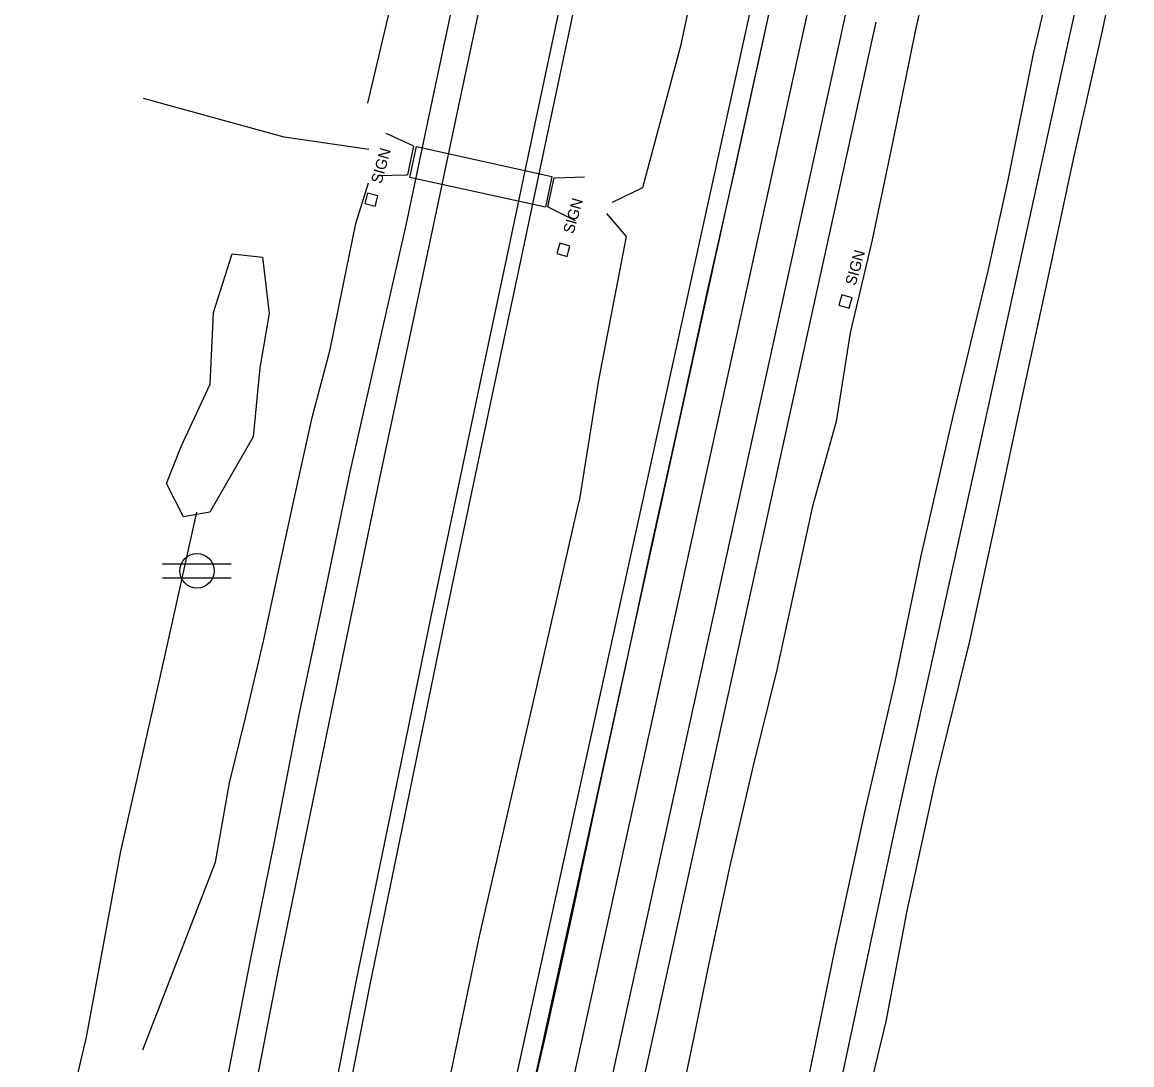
# Model space of a CAD drawing. Extents: x 14105231 to 14123593, y 8636972 to 8671693.
# Drawn here: x 14107983.5 to 14108338.7, y 8640678.7 to 8641012.4 of the extents above; entities that cross this region are included whole.
import ezdxf

# ---------------------------------------------------------------- set-up
doc = ezdxf.new("R2010")
doc.units = 0
for name, color, linetype in [('dsn3DCenterLine', 7, 'Continuous'), ('dsn3DPavementTop', 7, 'Continuous'), ('dsn3DShoulderTop', 7, 'Continuous'), ('PhoDrainageArrow', 7, 'Continuous'), ('PhoEdgeRoadPaved', 7, 'Continuous'), ('PhoEdgeShoulderPaved', 7, 'Continuous'), ('PhoEdgeShoulderUnpaved', 7, 'Continuous'), ('PhoFence', 7, 'Continuous'), ('PhoRailRoadTrack', 7, 'Continuous'), ('PhoRoadPoints', 7, 'Continuous'), ('PhoVegetation', 7, 'Continuous'), ('SurCulvert', 7, 'Continuous'), ('SurDrainageArrowUp', 7, 'Continuous'), ('SurUtilityPoleCell', 7, 'Continuous')]:
    doc.layers.add(name, color=color, linetype=linetype)

msp = doc.modelspace()

# ---------------------------------------------------------------- linework, layer by layer
at = {"layer": 'dsn3DCenterLine'}
msp.add_lwpolyline([(14108126.97, 8640523.99), (14108234.25, 8641012.34), (14108235.32, 8641017.22)], dxfattribs=at)
at = {"layer": 'dsn3DPavementTop'}
for points in [[(14108087.36, 8640399.59), (14108222.53, 8641014.92)], [(14108138.69, 8640521.41), (14108245.97, 8641009.77), (14108247.04, 8641014.65)]]:
    msp.add_lwpolyline(points, dxfattribs=at)
at = {"layer": 'dsn3DShoulderTop'}
for points in [[(14108123.34, 8640591.33), (14108124.41, 8640596.22), (14108216.67, 8641016.2)], [(14108123.34, 8640591.33), (14108126.55, 8640605.98), (14108216.67, 8641016.2)], [(14108148.46, 8640519.27), (14108255.74, 8641007.62), (14108256.81, 8641012.5)]]:
    msp.add_lwpolyline(points, dxfattribs=at)
at = {"layer": 'PhoDrainageArrow'}
for points in [[(14108160.05, 8641268.81), (14108153.6, 8641238.64), (14108146.75, 8641211.75), (14108142.61, 8641187.9), (14108135.7, 8641159.27), (14108129.24, 8641129.98), (14108122.16, 8641096.62), (14108115.58, 8641069.75), (14108111.05, 8641043.89), (14108101.1, 8641016.37), (14108094.04, 8640986.54)], [(14108278.23, 8641048.88), (14108269.34, 8641009.61), (14108262.19, 8640974.38), (14108255.59, 8640942.84), (14108248.55, 8640913.02), (14108244, 8640884.62), (14108236.43, 8640857.52), (14108225.07, 8640805.19), (14108217.47, 8640774.57), (14108210.02, 8640742.4), (14108203.42, 8640711.71), (14108198.23, 8640686.67), (14108192.15, 8640657.65), (14108184.81, 8640626.86), (14108179.61, 8640596.09), (14108173.2, 8640560.92)], [(14108022.13, 8640683.54), (14108045.45, 8640743.63), (14108049.84, 8640768.99), (14108054.96, 8640789.74), (14108060.82, 8640814.34), (14108066.79, 8640842.18), (14108070.97, 8640861.77), (14108076.34, 8640885.89), (14108082.11, 8640907.69), (14108086.14, 8640927.68), (14108090.34, 8640947.97), (14108094.38, 8640961.06)], [(14108119.26, 8640668.7), (14108129.95, 8640719.88), (14108147.91, 8640798.34), (14108161.76, 8640859.11)]]:
    msp.add_lwpolyline(points, dxfattribs=at)
at = {"layer": 'PhoEdgeRoadPaved'}
for points in [[(14108228.54, 8641043.39), (14108220.2, 8641004.55), (14108211.52, 8640965.11), (14108202.63, 8640925.97), (14108193.58, 8640884.18), (14108184.84, 8640844.87), (14108176.53, 8640805.92), (14108168.08, 8640767.14), (14108159.48, 8640726.63), (14108150.88, 8640687.84), (14108141.81, 8640649.05), (14108133.47, 8640610.14), (14108127.42, 8640581.81), (14108121.35, 8640556.22), (14108116.58, 8640531.9), (14108107.73, 8640492.91), (14108099.29, 8640453.48), (14108091.05, 8640415.44), (14108082.28, 8640375.85)], [(14108037.72, 8640564.73), (14108042.93, 8640591.98), (14108050.6, 8640631.07), (14108058.1, 8640670.74), (14108065.81, 8640710.28), (14108073.6, 8640748.26), (14108081.83, 8640788.19), (14108089.89, 8640827.35), (14108098.05, 8640866.55), (14108106.33, 8640905.55), (14108114.81, 8640945.75), (14108123.15, 8640985.27), (14108131.49, 8641024.51)], [(14108030.56, 8640378.39), (14108037.33, 8640418.75), (14108044.09, 8640458.29), (14108051.34, 8640497.72), (14108058.46, 8640536.87), (14108062.56, 8640559.77), (14108067.59, 8640587.2), (14108075.25, 8640626.23), (14108082.75, 8640665.91), (14108090.43, 8640705.28), (14108098.19, 8640743.14), (14108106.42, 8640783.06), (14108114.48, 8640822.19), (14108122.62, 8640861.32), (14108130.89, 8640900.3), (14108139.38, 8640940.52), (14108147.71, 8640980.01), (14108156.04, 8641019.17)]]:
    msp.add_lwpolyline(points, dxfattribs=at)
at = {"layer": 'PhoEdgeShoulderPaved'}
for points in [[(14108028.83, 8640566.6), (14108030.81, 8640581.42), (14108034.33, 8640599.23), (14108048.92, 8640672.78), (14108056.6, 8640712.22), (14108064.37, 8640750.65), (14108072.2, 8640790.7), (14108080.41, 8640829.47), (14108088.54, 8640868.57), (14108097.39, 8640907.56), (14108106.38, 8640947.53), (14108114.71, 8640987.05), (14108123.06, 8641026.31)], [(14108035.1, 8640377.84), (14108041.87, 8640418.18), (14108048.62, 8640457.65), (14108055.86, 8640497.03), (14108062.99, 8640536.2), (14108067.09, 8640559.1), (14108074.76, 8640598.12), (14108079.76, 8640625.45), (14108087.26, 8640665.14), (14108094.92, 8640704.44), (14108102.67, 8640742.25), (14108110.9, 8640782.17), (14108118.96, 8640821.29), (14108127.09, 8640860.39), (14108135.36, 8640899.36), (14108143.85, 8640939.58), (14108152.18, 8640979.07), (14108160.5, 8641018.19)]]:
    msp.add_lwpolyline(points, dxfattribs=at)
at = {"layer": 'PhoEdgeShoulderUnpaved'}
for points in [[(14108318.71, 8641051.69), (14108307.08, 8641002.33), (14108299.02, 8640961.93), (14108292.67, 8640933.25), (14108281.39, 8640886.36), (14108271.2, 8640841.64), (14108262.74, 8640800.86), (14108253.08, 8640759.61), (14108243.49, 8640715.43), (14108232.6, 8640662.26), (14108225.63, 8640626.79), (14108216.74, 8640592.65), (14108211.33, 8640567.43), (14108206.85, 8640549)], [(14108224.61, 8640543.45), (14108228.22, 8640556.56), (14108236.6, 8640592.89), (14108242.11, 8640616.24), (14108249.77, 8640650.12), (14108260.02, 8640692.6), (14108266.73, 8640728.06), (14108276.02, 8640770.55), (14108286.82, 8640814.3), (14108295.68, 8640855.24), (14108303.21, 8640890.82), (14108311.61, 8640929.16), (14108320.05, 8640968.63), (14108329.12, 8641008.72), (14108337.08, 8641046.47)]]:
    msp.add_lwpolyline(points, dxfattribs=at)
at = {"layer": 'PhoFence'}
msp.add_lwpolyline([(14107983.54, 8640593.02), (14107998.65, 8640664.55), (14108004.16, 8640687.58), (14108015.03, 8640746.56), (14108029.31, 8640809.92), (14108039.43, 8640855.61)], dxfattribs=at)
at = {"layer": 'PhoRailRoadTrack'}
msp.add_lwpolyline([(14108119.95, 8640104.52), (14108137.51, 8640184.4), (14108166.59, 8640316.33), (14108198.25, 8640460.33), (14108222.9, 8640571.84), (14108246.23, 8640676), (14108263.71, 8640757.87), (14108289.91, 8640876.29), (14108316.28, 8640996.71), (14108351.6, 8641156.22)], dxfattribs=at)
at = {"layer": 'PhoRoadPoints'}
for points in [[(14108096.94, 8640955.17), (14108096.94, 8640955.17), (14108097.4, 8640956.82), (14108094.1, 8640957.74), (14108093.17, 8640954.44), (14108096.47, 8640953.52), (14108096.94, 8640955.17)], [(14108158.39, 8640939.12), (14108158.39, 8640939.12), (14108158.86, 8640940.77), (14108155.56, 8640941.7), (14108154.63, 8640938.4), (14108157.93, 8640937.47), (14108158.39, 8640939.12)], [(14108248.69, 8640922.55), (14108248.69, 8640922.55), (14108249.15, 8640924.2), (14108245.85, 8640925.13), (14108244.92, 8640921.83), (14108248.22, 8640920.9), (14108248.69, 8640922.55)]]:
    msp.add_lwpolyline(points, dxfattribs=at)
at = {"layer": 'PhoVegetation'}
msp.add_lwpolyline([(14108043.61, 8640855.6), (14108035.13, 8640854.12), (14108029.7, 8640864.77), (14108034.43, 8640876.6), (14108043.74, 8640896.61), (14108044.73, 8640919.49), (14108050.73, 8640938.34), (14108060.41, 8640937.19), (14108062.55, 8640919.22), (14108059.59, 8640901.81), (14108057.43, 8640879.78)], close=True, dxfattribs=at)
at = {"layer": 'SurCulvert'}
for points in [[(14108099.93, 8640976.95), (14108108.58, 8640972.93), (14108108.58, 8640972.93), (14108108.8, 8640972.72), (14108106.82, 8640963.54), (14108106.49, 8640963.5), (14108097.21, 8640963.26)], [(14108107.61, 8640962.7), (14108109.7, 8640972.71), (14108153.05, 8640963.02), (14108150.99, 8640953.21), (14108107.61, 8640962.7)], [(14108160.58, 8640948.9), (14108152.14, 8640953.16), (14108151.77, 8640953.32), (14108153.76, 8640962.61), (14108154.11, 8640962.6), (14108163.52, 8640962.91)]]:
    msp.add_lwpolyline(points, dxfattribs=at)
at = {"layer": 'SurDrainageArrowUp'}
for points in [[(14108172.43, 8640954.86), (14108182.17, 8640959.49), (14108194.4, 8641005.36), (14108203.18, 8641046.53)], [(14108094.48, 8640971.65), (14108067.4, 8640975.62), (14108022.35, 8640988)], [(14108170.52, 8640951.22), (14108176.81, 8640943.82), (14108168.02, 8640897.84), (14108161.76, 8640859.11)]]:
    msp.add_lwpolyline(points, dxfattribs=at)
at = {"layer": 'SurUtilityPoleCell'}
for p, q in [((14108028.47, 8640839.05), (14108050.47, 8640839.05)), ((14108028.47, 8640834.65), (14108050.47, 8640834.65))]:
    msp.add_line(p, q, dxfattribs=at)
msp.add_circle((14108039.47, 8640836.85), 5.51, dxfattribs=at)

# ---------------------------------------------------------------- texts
at = {"layer": 'PhoRoadPoints'}
for p in [(14108098.49, 8640960.56), (14108159.95, 8640944.51), (14108250.24, 8640927.94)]:
    msp.add_text('SIGN', height=3.499, rotation=74.2984, dxfattribs=at).set_placement(p)

doc.saveas('drawing.dxf')
